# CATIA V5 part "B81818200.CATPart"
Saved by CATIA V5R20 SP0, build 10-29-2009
Part number: B81818200
Revision: 4
Definition: design
Nomenclature: B81818200
Source: made
Description: NOT SPECIFIED
Bounding box of the stored display mesh (mm): x -10.833 to 10.833, y -11 to 11, z 0 to 200
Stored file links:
  C:\Users\Raffaele\Desktop\3D X SITO CF\BOLEX\6-PILLAR REF 818\B81818200.CATPart
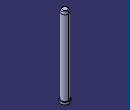
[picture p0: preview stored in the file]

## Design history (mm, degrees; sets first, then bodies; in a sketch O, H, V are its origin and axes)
Body1 "MANIFOLD_SOLID_BREP #370" (main body)
  Solid1: solid without history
